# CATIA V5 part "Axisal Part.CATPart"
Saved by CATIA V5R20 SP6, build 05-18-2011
Part number: Axisal Part
Bounding box of the stored display mesh (mm): x -20 to 20, y -450 to 450, z -20 to 20
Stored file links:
  E:\#03 University\#02 영남 이공대\#01 2021\#02 여름 방학\#01 Documents\K-Move Page02 ASD01\Axisal Part.CATPart

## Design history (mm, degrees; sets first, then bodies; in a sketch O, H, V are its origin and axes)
Set1 "Reference Data"
  Point1 "Center Point": (0, 0, 0)
Body1 (main body)
  Body2
    Sketch1 on zx-plane, origin (0, 0, 0), H (-1, 0, 0), V (0, 0, 1)
      circle A1 centre (0, 0) radius 20
      radius A1 = 20
    Pad1: profile Sketch1, direction (0, 1, 0), length 450, mirrored extent
  Assemble1: tool Body2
